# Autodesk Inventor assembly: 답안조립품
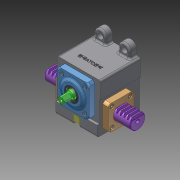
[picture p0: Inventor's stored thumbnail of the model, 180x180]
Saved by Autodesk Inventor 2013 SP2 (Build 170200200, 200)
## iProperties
Created: 2024-11
Part Number: 답안조립품
Document SubType Name: Assembly
Designer: a
Author: a
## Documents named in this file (10)
- C:\Users\a\Desktop\741104V1014\답안조립품.iam
- C:\Users\a\Desktop\741104V1014\본체.ipt
- C:\Users\a\Desktop\741104V1014\깊음 홈 볼 베어링 6202.ipt
- C:\Users\a\Desktop\741104V1014\래크.ipt
- C:\Users\a\Desktop\741104V1014\수지 부시.ipt
- C:\Users\a\Desktop\741104V1014\스톱퍼.ipt
- C:\Users\a\Desktop\741104V1014\오일 실 15 25 4.ipt
- C:\Users\a\Desktop\741104V1014\육각 소켓 머리 볼트 M4x10.ipt
- C:\Users\a\Desktop\741104V1014\커버.ipt
- C:\Users\a\Desktop\741104V1014\피니언 축.ipt
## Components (1 placed, 1 different names)
1. 피니언 축:1
